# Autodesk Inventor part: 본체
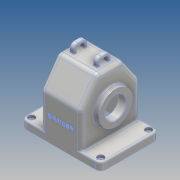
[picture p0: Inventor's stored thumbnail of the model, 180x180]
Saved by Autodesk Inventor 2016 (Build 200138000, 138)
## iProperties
Created: 2016-12
Part Number: 본체
Material: 알루미늄 6061
Document SubType Name: Modeling
Designer: Administrator
Density: 2.7 g/cm^3
Appearance: 알루미늄 - 평지
Mass: 1063.31 g
Surface Area: 1138.22 cm^2
Volume: 393.819 cm^3
Author: Administrator
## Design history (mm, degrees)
sketch "스케치1"
  geometry: L1 (-65, 55)-(65, 55); L2 (75, 45)-(75, -45); L3 (65, -55)-(-65, -55); L4 (-75, -45)-(-75, 45); L5 (-75, 55)-(75, -55); L6 (75, 55)-(-75, -55); A1 r 10 centre (-65, 45) between (-65, 55) and (-75, 45); A2 r 10 centre (-65, -45) between (-75, -45) and (-65, -55); A3 r 10 centre (65, -45) between (65, -55) and (75, -45); A4 r 10 centre (65, 45) between (75, 45) and (65, 55); 1 further point
  constraints: 12 end point, 8 point on circle, 8 point on line, 8 tangent, 4 centre point, 3 equal radius, 2 midpoint, 2 parallel, 1 horizontal, 1 perpendicular
  dimensions: "d0" = 150 distance of L5.end L6.end; "d1" = 110 distance of L6.start L5.end; "d2" = 10 radius of A1
extrude "돌출1" new body sketch "스케치1" distance "d3" = 15; taper "d4" = 0 deg
sketch "스케치2"
  geometry: L1 (-45, 15)-(-55, 15) reference; L2 (45, 15)-(-45, 15) reference; L3 (55, 15)-(45, 15) reference; L4 (-55, 15)-(-55, 76.847); L5 (-53.192, 82.583)-(-26.477, 120.736); L6 (-18.285, 125)-(18.285, 125); L7 (26.477, 120.736)-(53.192, 82.583); L8 (55, 76.847)-(55, 15); L9 (45, 0)-(-45, 0) reference; A1 r 10 centre (-18.285, 115) between (-18.285, 125) and (-26.477, 120.736); A2 r 10 centre (18.285, 115) between (26.477, 120.736) and (18.285, 125); A3 r 10 centre (45, 76.847) between (55, 76.847) and (53.192, 82.583); A4 r 10 centre (-45, 76.847) between (-53.192, 82.583) and (-55, 76.847); 3 further points
  constraints: 10 end point, 8 point on circle, 8 tangent, 4 centre point, 4 point on line, 3 equal radius, 2 vertical, 1 perpendicular
  dimensions: "d5" = 80 distance from line of point (55, 80) L9; "d6" = 80 distance from line of L9 point (-55, 80) (= d5); "d7" = 125 distance between parallel lines of L9 L6; "d8" = 35 deg angle of L5 L4; "d9" = 35 deg angle of L8 L7; "d10" = 10 radius of A1
extrude "돌출2" join sketch "스케치2" stored distance "d11" = 77; taper "d12" = 0 deg
sketch "스케치3"
  geometry: L1 (43.5, 65)-(-48.5, 65); L2 (-65, 0)-(65, 0) reference; L3 (38.5, 76.847)-(38.5, 15) reference; L4 (-38.5, 15)-(-38.5, 76.847) reference; L5 (43.5, 65)-(43.5, 102.5); L6 (43.5, 102.5)-(38.5, 102.5); L7 (38.5, 120.736)-(38.5, 82.583) reference; L8 (-38.5, 82.583)-(-38.5, 120.736) reference; L9 (-38.5, 96)-(-48.5, 96); L10 (-48.5, 96)-(-48.5, 65); L11 (-38.5, 96)-(38.5, 96); L12 (38.5, 102.5)-(38.5, 96); 1 further point
  constraints: 14 end point, 4 point on line, 3 perpendicular, 2 horizontal, 1 vertical
  dimensions: "d14" = 75 diameter of L6 L1; "d15" = 5 distance between parallel lines of L7 L5; "d17" = 65 distance between parallel lines of L2 L1; "d18" = 62 diameter of L9 L1; "d19" = 87 distance between parallel lines of L7 L10
revolve "회전1" sketch "스케치3" stored, may be unused: angle "d20" = 90 deg
sketch "스케치4"
  geometry: L1 (45, 0)-(-45, 0) reference; L2 (-53.192, 82.583)-(-26.477, 120.736) reference; L3 (-18.285, 125)-(18.285, 125) reference; L4 (26.477, 120.736)-(53.192, 82.583) reference; L5 (55, 76.847)-(55, 15) reference; L6 (-55, 15)-(-55, 76.847) reference; L7 (-55, 0)-(-55, 15) reference; L8 (55, 0)-(55, 15) reference; L9 (50, -5)-(50, 15); L10 (50, 15)-(50, 76.847); L11 (49.096, 79.715)-(22.381, 117.868); L12 (18.285, 120)-(-18.285, 120); L13 (-22.381, 117.868)-(-49.096, 79.715); L14 (-50, 76.847)-(-50, 15); L15 (-50, 15)-(-50, -5); L16 (-45, 0)-(-55, 0) reference; L17 (55, 0)-(45, 0) reference; L18 (-50, -5)-(50, -5); A1 r 10 centre (-18.285, 115) between (-18.285, 125) and (-26.477, 120.736) reference; A2 r 10 centre (18.285, 115) between (26.477, 120.736) and (18.285, 125) reference; A3 r 10 centre (45, 76.847) between (55, 76.847) and (53.192, 82.583) reference; A4 r 10 centre (-45, 76.847) between (-53.192, 82.583) and (-55, 76.847) reference; A5 r 5 centre (45, 76.847) between (50, 76.847) and (49.096, 79.715); A6 r 5 centre (18.285, 115) between (22.381, 117.868) and (18.285, 120); A7 r 5 centre (-18.285, 115) between (-18.285, 120) and (-22.381, 117.868); A8 r 5 centre (-45, 76.847) between (-49.096, 79.715) and (-50, 76.847); 1 further point
  constraints: 18 end point, 8 point on circle, 4 centre point, 2 collinear, 1 horizontal, 8 other
  dimensions: "d21" = 5 distance between parallel lines of L3 L12; "d22" = 5 distance between parallel lines of L1 L18
extrude "돌출3" cut sketch "스케치4" stored distance "d23" = 67; taper "d24" = 0 deg
fillet "모깎기1" dims "d25" = 8
fillet "모깎기2" dims "d26" = 3
sketch "스케치5"
  geometry: L1 (33.5, 106)-(19.5, 92); L2 (33.5, 65)-(-33.5, 65); L3 (-65, 0)-(65, 0) reference; L4 (33.5, 76.847)-(33.5, 0) reference; L5 (-33.5, 0)-(-33.5, 76.847) reference; L6 (43.5, 27.5)-(43.5, 102.5) reference; L7 (19.5, 65)-(19.5, 92); L8 (33.5, 116.147)-(33.5, 77.994) reference; L9 (33.5, 106)-(33.5, 65); 1 further point
  constraints: 9 end point, 4 point on line, 1 horizontal, 1 parallel
  dimensions: "d27" = 65 distance between parallel lines of L3 L2; "d28" = 24 distance between parallel lines of L6 L7; "d29" = 45 deg angle of L7 L1; "d30" = 27 distance of L7.start L1.end
revolve "회전2" sketch "스케치5" stored, may be unused: angle "d31" = 90 deg
sketch "스케치6"
  geometry: L1 (43.5, 27.5)-(43.5, 102.5) reference; L2 (43.5, 65)-(-48.5, 65); L3 (-48.5, 34)-(-48.5, 96) reference; L4 (43.5, 85)-(-48.5, 85); L5 (43.5, 85)-(43.5, 65); L6 (-48.5, 65)-(-48.5, 85); 1 further point
  constraints: 8 end point, 2 midpoint, 1 collinear, 1 parallel, 1 perpendicular
  dimensions: "d32" = 20 distance between parallel lines of L2 L4
revolve "회전3" sketch "스케치6" stored, may be unused: angle "d33" = 90 deg
fillet "모깎기3" dims "d34" = 3
sketch "스케치7"
  geometry: L1 (4.5, -5.785)-(12.5, -5.785); L2 (12.5, -5.785)-(12.5, -30.785); L3 (12.5, -30.785)-(4.5, -30.785); L4 (4.5, -30.785)-(4.5, -5.785); L5 (48.5, -5.785)-(56.5, -5.785); L6 (56.5, -5.785)-(56.5, -30.785); L7 (56.5, -30.785)-(48.5, -30.785); L8 (48.5, -30.785)-(48.5, -5.785); 2 further points
  constraints: 16 end point, 4 parallel, 2 horizontal, 2 perpendicular, 2 point on line, 1 horizontal alignment, 1 midpoint
  dimensions: "d35" = 25 distance of L3.end L1.start; "d36" = 8 distance of L1.start L1.end; "d37" = 8 distance of L5.start L5.end (= d36); "d38" = 18 distance from line of point (30.5, -18.285) L8; "d39" = 36 distance between parallel lines of L8 L2
extrude "돌출4" join sketch "스케치7" distance "d40" = 15; taper "d41" = 0 deg
sketch "스케치8"
  geometry: L1 (0, 25)-(0, 0) reference; L2 (-15, 0)-(-15, 25) reference; L3 (0, 0)-(-15, 0) reference; L4 (-10, 20)-(0, 20); L5 (0, 5)-(-10, 5); L6 (-10, 5)-(-10, 20); 1 further point
  constraints: 6 end point, 2 point on line, 1 other
  dimensions: "d42" = 5 distance between parallel lines of L2 L6; "d43" = 15 distance between parallel lines of L5 L4
extrude "돌출5" cut sketch "스케치8" stored distance "d44" = 15; taper "d45" = 0 deg
fillet "모깎기4" dims "d46" = 8
fillet "모깎기5" dims "d47" = 3
fillet "모깎기6" dims "d48" = 1
fillet "모깎기7" dims "d49" = 1
sketch "스케치9"
  geometry: A1 r 7 centre (65, -45) between (65, -52) and (72, -45) reference; A2 r 7 centre (65, 45) between (72, 45) and (65, 52) reference; A3 r 10 centre (-65, 45) between (-65, 55) and (-75, 45) reference; A4 r 10 centre (-65, -45) between (-75, -45) and (-65, -55) reference; 5 further points
  constraints: 4 coincident
hole "구멍1" sketch "스케치9" at (-65, 45), (-65, -45), (65, -45), (65, 45) diameter "d50" = 5; stored, may be unused: countersink angle "d54" = 90 deg, drill point angle "d56" = 0 deg; dims "d51" = 6, "d52" = 12, "d53" = 5, "d55" = 8
sketch "스케치10"
  geometry: C1 r 20 at (0, 0) reference; C2 r 31 at (0, 0) reference; A1 r 26 centre (0, 0) between (-26, 0) and (26, 0); 3 further points
  constraints: 4 point on circle, 2 horizontal alignment, 2 vertical alignment, 1 centre point, 1 coincident
  dimensions: "d57" = 52 diameter of A1
hole "구멍2" sketch "스케치10" at (-26, 0), (26, 0), (0, -26), (0, 26) diameter "d58" = 2.459; stored, may be unused: countersink angle "d62" = 90 deg, drill point angle "d64" = 0 deg; dims "d59" = 6, "d60" = 12, "d61" = 5, "d63" = 8
sketch "스케치11"
  geometry: C1 r 20 at (0, 0) reference; C2 r 37.5 at (0, 0) reference; A1 r 29 centre (0, 0) between (29, 0) and (0, 29); 3 further points
  constraints: 4 point on circle, 2 horizontal alignment, 2 vertical alignment, 1 centre point, 1 coincident
  dimensions: "d65" = 58 diameter of A1
hole "구멍3" sketch "스케치11" at (29, 0), (0, 29), (-29, 0), (0, -29) diameter "d66" = 2.459; stored, may be unused: countersink angle "d70" = 90 deg, drill point angle "d72" = 0 deg; dims "d67" = 6, "d68" = 12, "d69" = 5, "d71" = 8
chamfer "모따기1" distance "d73" = 1; stored, may be unused: second distance "d74" = 2, angle "d75" = 45 deg
sketch "스케치12"
  geometry: L1 (0, 0)-(130, 0) reference; C1 r 10 at (65, 45); 3 further points
  constraints: 1 centre point, 1 coincident, 1 midpoint, 1 vertical alignment, 1 other
  dimensions: "d76" = 20 diameter of C1; "d77" = 45 distance from line of C1.centre L1
feature "엠보싱1" sketch "스케치12" dims "d0" = 150, "d1" = 110, "d2" = 10, "d5" = 80, "d6" = 80 (= d5), "d7" = 125, "d8" = 35 deg, "d9" = 35 deg, "d10" = 10, "d78" = 0.5, "d79" = 0
node "솔리드1"
